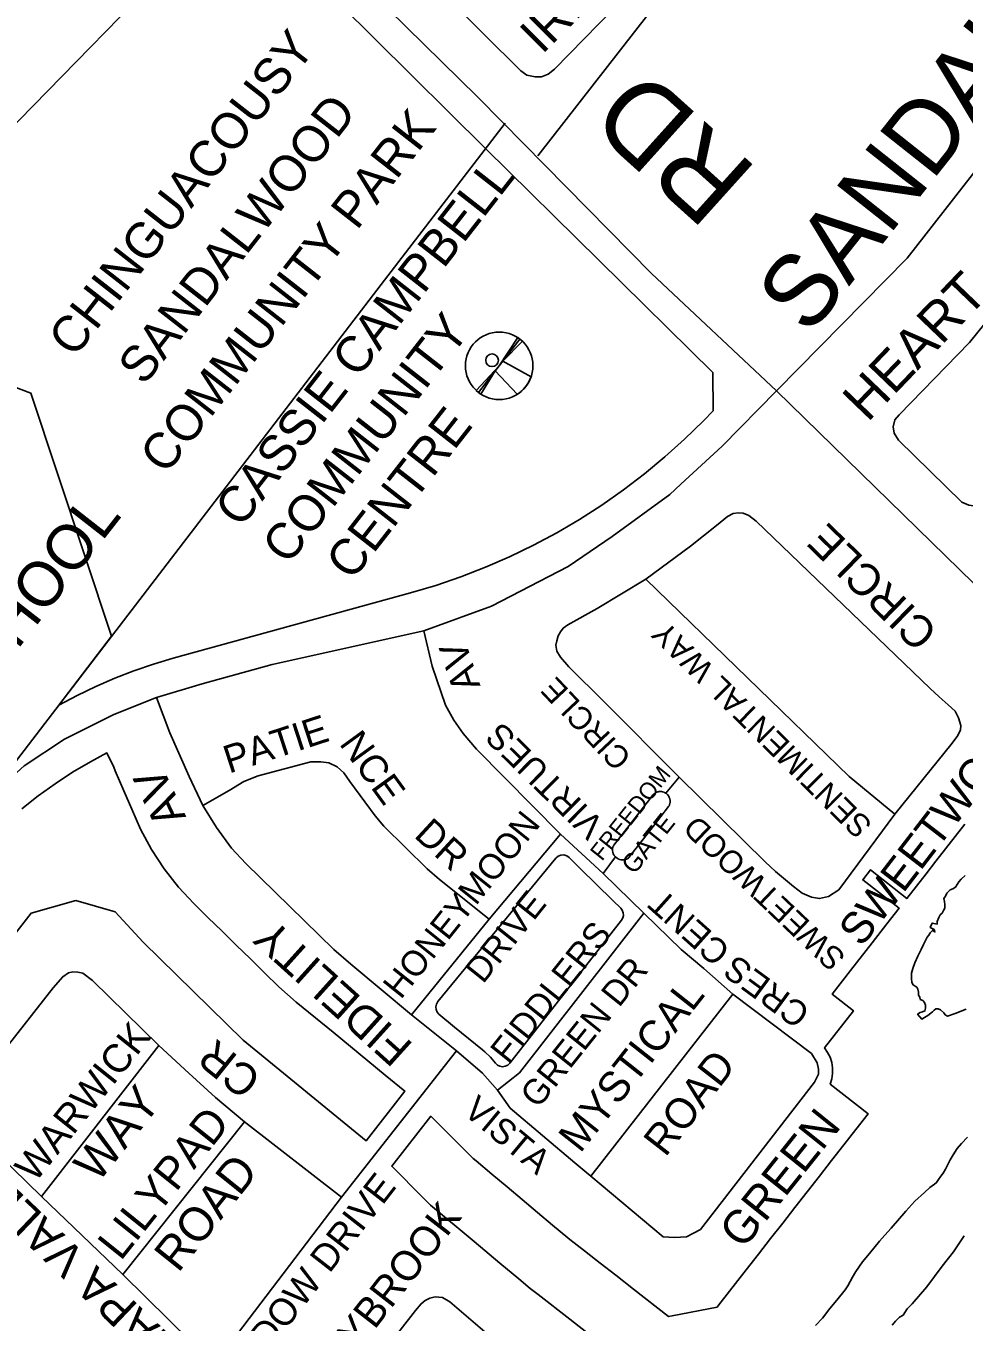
# Model space of a CAD drawing. Extents: x 586326 to 623965, y 4819854 to 4857850.
# Drawn here: x 594445 to 594966, y 4838360 to 4839080 of the extents above; entities that cross this region are included whole.
import ezdxf

# ---------------------------------------------------------------- set-up
doc = ezdxf.new("R2010")
doc.units = 0
for name, color, linetype in [('Lots_Concessions', 7, 'Continuous'), ('Major Rds and Hwys', 7, 'Continuous'), ('Major Rds Lbls', 7, 'Continuous'), ('Minor Rd Lbls', 7, 'Continuous'), ('Minor Rds', 7, 'Continuous'), ('Park Lbls', 7, 'Continuous'), ('Park Outlines', 7, 'Continuous'), ('Rec Lbls', 7, 'Continuous'), ('Rec Syms', 7, 'Continuous'), ('School Syms_Lbls', 7, 'Continuous'), ('SWM Ponds', 7, 'Continuous')]:
    doc.layers.add(name, color=color, linetype=linetype)

msp = doc.modelspace()

# ---------------------------------------------------------------- linework, layer by layer
at = {"layer": 'Lots_Concessions'}
for p, q in [((594729.47, 4839007.45), (595156.29, 4839555.22)), ((594642.61, 4838935.95), (594711.39, 4839025.63)), ((594295.72, 4838483.65), (594642.61, 4838935.95))]:
    msp.add_line(p, q, dxfattribs=at)
at = {"layer": 'Major Rds and Hwys'}
for points in [[(594861.99, 4838876.99), (594934.54, 4838950.7), (595088.89, 4839148.46)], [(594709.8, 4839026.23), (594696.13, 4839040.1), (594606.93, 4839127.81)], [(594861.99, 4838876.99), (594792.7, 4838942.09), (594709.8, 4839026.23)], [(594808.99, 4838825.16), (594831.95, 4838846.26), (594861.99, 4838876.99)], [(595281.37, 4838462.67), (595165.16, 4838580.18), (595155.16, 4838590.01), (595018.37, 4838724.46), (594861.99, 4838876.99)], [(594666.27, 4838743.78), (594703.78, 4838757.46), (594746.36, 4838779.49), (594770.84, 4838796.08), (594802.91, 4838819.41), (594808.99, 4838825.16)], [(594517.84, 4838706.7), (594543.23, 4838714.45), (594582.03, 4838725.17), (594666.27, 4838743.78)], [(594290.63, 4838488.36), (594398.62, 4838625.17), (594419.01, 4838646.13), (594444.39, 4838668.83), (594466.8, 4838683.62), (594494.09, 4838697.43), (594517.84, 4838706.7)]]:
    msp.add_lwpolyline(points, dxfattribs=at)
at = {"layer": 'Minor Rds'}
for points in [[(594947.94, 4839266.3), (594874.03, 4839214.2), (594868.8, 4839209.7), (594863.92, 4839203.89), (594791.44, 4839110.68), (594785.39, 4839103.38), (594779.91, 4839097.69), (594738.78, 4839055.6), (594735.26, 4839052.85), (594731.6, 4839051.24), (594728.13, 4839051.2), (594723.38, 4839052.16), (594720.18, 4839054.66), (594678.5, 4839096.03)], [(595045.04, 4838887.27), (595022.97, 4838860.3), (594980.45, 4838817.27), (594976.3, 4838814.28), (594972.51, 4838813.03), (594968.85, 4838813.48), (594964.93, 4838815.14), (594929.81, 4838849.61), (594927.29, 4838853.58), (594926.76, 4838857.01), (594927.75, 4838860.85), (594930.12, 4838863.62), (594969.14, 4838903.81), (594981.57, 4838919.2), (595018.06, 4838965.39)], [(594828.64, 4838802.32), (594834.83, 4838807.27), (594837.99, 4838808.92), (594840.73, 4838809.26), (594843.55, 4838809.18), (594846.73, 4838807.81), (594850.79, 4838804.64), (594947.29, 4838711.7), (594952.33, 4838707.12), (594957.35, 4838702.74), (594961.18, 4838699.19), (594963.07, 4838695.53), (594964.32, 4838691.24), (594964.21, 4838688.92), (594962.67, 4838685.78), (594959.66, 4838681.49), (594927.66, 4838641.98)], [(594789.42, 4838772.42), (594814.37, 4838790.77), (594828.64, 4838802.32)], [(594808, 4838662.64), (594766.39, 4838704.31), (594746.74, 4838723.82), (594742.18, 4838729.15), (594740.04, 4838732.6), (594739.58, 4838735.78), (594740, 4838738.28), (594740.85, 4838741.04), (594742.1, 4838743.24), (594743.63, 4838745.35), (594746.25, 4838747.19), (594762.49, 4838756.2), (594789.42, 4838772.42)], [(594927.66, 4838641.98), (594902.35, 4838662.94), (594789.42, 4838772.42)], [(594742.13, 4838630.93), (594695.54, 4838678.14), (594688.02, 4838686.77), (594682.98, 4838694.16), (594678.33, 4838702.62), (594670.78, 4838724.16), (594666.27, 4838743.78)], [(594543.46, 4838646.84), (594536.05, 4838663), (594525.26, 4838687.23), (594517.84, 4838706.7)], [(594702.48, 4838583.71), (594674.86, 4838605.76), (594668.05, 4838611.76), (594643.98, 4838635.4), (594639.27, 4838641.15), (594625.18, 4838660.21), (594621.76, 4838664.95), (594618.12, 4838668.25), (594613.46, 4838670.52), (594609.12, 4838671.15), (594603.57, 4838671.11), (594574.2, 4838663.24), (594566.31, 4838660.21), (594558.16, 4838655.08), (594543.46, 4838646.84)], [(594800.51, 4838653.7), (594808, 4838662.64)], [(594808, 4838662.64), (594855.67, 4838615.63), (594861.48, 4838610.18), (594871.5, 4838601.9), (594876.33, 4838598.12), (594881.48, 4838595.93), (594885.94, 4838595.19), (594890.94, 4838596.31), (594896.64, 4838600.1), (594927.66, 4838641.98)], [(594772.67, 4838618.3), (594772.27, 4838618.74), (594772.13, 4838618.9), (594772, 4838619.06), (594771.89, 4838619.24), (594771.79, 4838619.43), (594771.45, 4838620.09), (594771.36, 4838620.28), (594771.29, 4838620.48), (594771.23, 4838620.68), (594771.18, 4838620.89), (594771.04, 4838621.62), (594771.01, 4838621.83), (594770.99, 4838622.04), (594770.99, 4838622.25), (594771.01, 4838622.46), (594771.08, 4838623.2), (594771.11, 4838623.44), (594771.16, 4838623.67), (594771.23, 4838623.91), (594771.32, 4838624.13), (594771.43, 4838624.35), (594771.55, 4838624.55), (594771.69, 4838624.75), (594780.23, 4838635.76), (594780.24, 4838635.77), (594791.5, 4838650.13), (594793.37, 4838652.7), (594793.52, 4838652.9), (594793.7, 4838653.08), (594793.88, 4838653.25), (594794.08, 4838653.4), (594794.7, 4838653.83), (594794.9, 4838653.96), (594795.1, 4838654.07), (594795.31, 4838654.16), (594795.52, 4838654.24), (594796.25, 4838654.46), (594796.47, 4838654.52), (594796.69, 4838654.56), (594796.92, 4838654.59), (594797.15, 4838654.6), (594797.91, 4838654.59), (594798.14, 4838654.59), (594798.36, 4838654.56), (594798.59, 4838654.51), (594798.81, 4838654.45), (594799.53, 4838654.22), (594799.75, 4838654.15), (594799.95, 4838654.05), (594800.51, 4838653.7)], [(594800.51, 4838653.7), (594800.97, 4838653.38), (594801.15, 4838653.24), (594801.32, 4838653.09), (594801.48, 4838652.93), (594801.62, 4838652.75), (594802.08, 4838652.15), (594802.22, 4838651.96), (594802.33, 4838651.76), (594802.43, 4838651.56), (594802.52, 4838651.34), (594802.78, 4838650.63), (594802.85, 4838650.41), (594802.9, 4838650.19), (594802.94, 4838649.96), (594802.95, 4838649.74), (594802.98, 4838648.98), (594802.98, 4838648.75), (594802.97, 4838648.52), (594802.93, 4838648.3), (594802.88, 4838648.07), (594802.68, 4838647.34), (594802.61, 4838647.12), (594802.52, 4838646.9), (594802.42, 4838646.68), (594802.3, 4838646.48), (594802.16, 4838646.29), (594793.56, 4838635.2), (594793.55, 4838635.19), (594780.14, 4838618.05), (594779.97, 4838617.86), (594779.79, 4838617.68), (594779.59, 4838617.51), (594779.38, 4838617.37), (594779.15, 4838617.24), (594778.92, 4838617.13), (594778.68, 4838617.04), (594777.97, 4838616.82), (594777.77, 4838616.76), (594777.56, 4838616.72), (594777.35, 4838616.69), (594777.14, 4838616.68), (594776.39, 4838616.66), (594776.18, 4838616.67), (594775.97, 4838616.68), (594775.76, 4838616.72), (594775.56, 4838616.76), (594774.84, 4838616.95), (594774.64, 4838617.01), (594774.44, 4838617.09), (594774.25, 4838617.18), (594774.06, 4838617.28), (594773.56, 4838617.65), (594772.67, 4838618.3)], [(594659.42, 4838530.66), (594625.75, 4838558.8), (594616.23, 4838566.93), (594567.51, 4838614.65), (594559.49, 4838623.22), (594551.12, 4838634.59), (594543.46, 4838646.84)], [(594702.48, 4838583.71), (594742.13, 4838630.93)], [(594765.84, 4838609.18), (594742.13, 4838630.93)], [(594765.84, 4838609.18), (594772.67, 4838618.3)], [(594788.42, 4838587.01), (594765.84, 4838609.18)], [(594659.42, 4838530.66), (594702.48, 4838583.71)], [(594707.2, 4838488.88), (594719.3, 4838498.54), (594788.42, 4838587.01)], [(594837.87, 4838542.15), (594821.68, 4838556.46), (594809.15, 4838566.99), (594788.42, 4838587.01)], [(594454.03, 4838429.74), (594414.11, 4838468.41), (594411.55, 4838472.03), (594410.72, 4838474.82), (594410.55, 4838477.78), (594410.86, 4838480.36), (594411.95, 4838483.19), (594413.98, 4838486.66), (594460.46, 4838545.71), (594465.77, 4838551.84), (594468.92, 4838553.91), (594471.4, 4838554.46), (594474.1, 4838554.4), (594476.92, 4838553.74), (594482.32, 4838549.69), (594519.04, 4838513.62)], [(594758.93, 4838441.11), (594837.87, 4838542.15)], [(594837.87, 4838542.15), (594881.44, 4838509.24), (594884.62, 4838503.93), (594885.36, 4838500.55), (594885.39, 4838497.71), (594883.09, 4838493.31), (594819.79, 4838411.58), (594812.08, 4838407.47), (594805.5, 4838406.98), (594799.12, 4838407.47), (594758.93, 4838441.11)], [(594684.29, 4838510.69), (594659.42, 4838530.66)], [(594454.03, 4838429.74), (594519.04, 4838513.62)], [(594566.63, 4838471.25), (594550.54, 4838484.86), (594535.79, 4838498.2), (594519.04, 4838513.62)], [(594620.55, 4838429.39), (594684.29, 4838510.69)], [(594707.2, 4838488.88), (594698.78, 4838498.24), (594684.29, 4838510.69)], [(594758.93, 4838441.11), (594750.12, 4838448.55), (594714.12, 4838478.94), (594707.2, 4838488.88)], [(594499.13, 4838386.44), (594566.63, 4838471.25)], [(594620.55, 4838429.39), (594566.63, 4838471.25)], [(594499.13, 4838386.44), (594454.03, 4838429.74)], [(594549.79, 4838336.5), (594620.55, 4838429.39)], [(594549.79, 4838336.5), (594499.13, 4838386.44)], [(594645.06, 4838242.82), (594713.21, 4838328.18), (594715.48, 4838333.06), (594715.81, 4838337.42), (594714.37, 4838342.13), (594711.75, 4838344.69), (594680.75, 4838371.33), (594676.65, 4838373.85), (594672.62, 4838374.17), (594669.5, 4838373.44), (594666.95, 4838372.16), (594664.71, 4838370.3), (594661.64, 4838366.5), (594599.44, 4838286.89)]]:
    msp.add_lwpolyline(points, dxfattribs=at)
at = {"layer": 'Park Outlines'}
for points in [[(594355.24, 4838910.92), (594448.07, 4838875.8), (594492.92, 4838740.76), (594463.65, 4838702.59), (594473.77, 4838707.98), (594484.1, 4838712.95), (594494.61, 4838717.51), (594505.31, 4838721.65), (594516.16, 4838725.35), (594527.15, 4838728.62), (594658.77, 4838764.86), (594672.84, 4838769.04), (594686.73, 4838773.78), (594700.42, 4838779.09), (594713.88, 4838784.93), (594727.1, 4838791.32), (594740.05, 4838798.24), (594752.71, 4838805.67), (594765.05, 4838813.61), (594777.07, 4838822.03), (594788.74, 4838830.94), (594800.04, 4838840.31), (594810.96, 4838850.13), (594821.46, 4838860.38), (594826.94, 4838865.94), (594826.78, 4838887.14), (594700.51, 4839011.49), (594639.25, 4839072.23), (594561.14, 4839149.7), (594409.35, 4838994.44)], [(594368.63, 4838485), (594448.2, 4838587.17), (594473.04, 4838594.1), (594494.93, 4838587.81), (594510.36, 4838571.08), (594566, 4838516.58), (594634.16, 4838460.77), (594655.66, 4838488.38), (594644.85, 4838497.23), (594635.18, 4838505.15), (594625.52, 4838513.07), (594615.85, 4838520.98), (594606.18, 4838528.9), (594595.41, 4838537.72), (594585.69, 4838546.27), (594577.83, 4838553.96), (594569.98, 4838561.66), (594562.12, 4838569.35), (594554.26, 4838577.05), (594546.41, 4838584.74), (594538.55, 4838592.44), (594530.04, 4838601.51), (594522.08, 4838611.62), (594515.06, 4838622.38), (594508.91, 4838633.65), (594504.1, 4838644.84), (594499.75, 4838654.94), (594494.94, 4838666.13), (594494.94, 4838666.13), (594494.11, 4838668.07), (594490.32, 4838676.02), (594481.2, 4838671.17), (594471.21, 4838665.28), (594461.5, 4838658.93), (594452.1, 4838652.15), (594443.02, 4838644.93)], [(594966.57, 4838636.42), (594961.21, 4838629.57), (594955.86, 4838622.71), (594950.5, 4838615.86), (594945.15, 4838609), (594939.79, 4838602.15), (594934.44, 4838595.29), (594914.23, 4838611.08), (594909.92, 4838605.56), (594930.13, 4838589.78), (594923.36, 4838581.11), (594915.16, 4838570.61), (594903.18, 4838555.28), (594892.94, 4838542.17), (594897.94, 4838538.27), (594904.79, 4838532.92), (594888.7, 4838512.31), (594890.44, 4838509.81), (594891.78, 4838507.08), (594892.7, 4838504.18), (594893.17, 4838501.17), (594893.18, 4838498.13), (594892.73, 4838495.12), (594891.84, 4838492.21), (594912.91, 4838475.75), (594906.14, 4838467.08), (594899.37, 4838458.42), (594892.6, 4838449.75), (594885.84, 4838441.09), (594879.07, 4838432.42), (594872.3, 4838423.76), (594865.53, 4838415.09), (594858.76, 4838406.43), (594851.99, 4838397.76), (594845.22, 4838389.1), (594830.08, 4838369.7), (594829.02, 4838368.36), (594804.15, 4838363.63), (594802.04, 4838363.23), (594782.64, 4838378.39), (594772.75, 4838386.11), (594764.08, 4838392.88), (594755.42, 4838399.65), (594747.33, 4838405.96), (594746.2, 4838406.91), (594737.77, 4838413.97), (594729.33, 4838421.03), (594720.9, 4838428.09), (594712.47, 4838435.16), (594704.03, 4838442.22), (594695.29, 4838449.53), (594693.65, 4838450.91), (594686.34, 4838458.21), (594678.56, 4838465.97), (594670.11, 4838474.4), (594648.45, 4838446.59), (594665.92, 4838429.16), (594670.02, 4838425.06), (594694.11, 4838404.9), (594708.5, 4838392.84), (594719, 4838384.05), (594725.33, 4838378.76), (594729.63, 4838375.4), (594747.22, 4838361.66), (594768.77, 4838344.82)]]:
    msp.add_lwpolyline(points, dxfattribs=at)
msp.add_lwpolyline([(594739.56, 4838617.65), (594674, 4838537.97), (594673.21, 4838536.63), (594672.87, 4838535.11), (594673.01, 4838533.56), (594673.63, 4838532.13), (594674.65, 4838530.96), (594683.3, 4838523.88), (594698.78, 4838511.21), (594700.1, 4838510.12), (594703.27, 4838507.18), (594706.05, 4838503.87), (594707.14, 4838502.81), (594708.49, 4838502.13), (594709.99, 4838501.88), (594711.49, 4838502.09), (594712.86, 4838502.74), (594713.97, 4838503.78), (594776, 4838583.19), (594776.72, 4838584.44), (594777.04, 4838585.85), (594776.95, 4838587.3), (594776.44, 4838588.66), (594775.57, 4838589.81), (594775.56, 4838589.83), (594771.22, 4838594.09), (594752.94, 4838612.1), (594746.91, 4838618.04), (594745.56, 4838618.98), (594743.97, 4838619.43), (594742.33, 4838619.34), (594740.8, 4838618.72)], close=True, dxfattribs=at)
at = {"layer": 'Rec Syms'}
for p, q in [((594719.63, 4838905.67), (594696.56, 4838876.14)), ((594696.56, 4838876.14), (594705.86, 4838888.05))]:
    msp.add_line(p, q, dxfattribs=at)
msp.add_lwpolyline([(594708, 4838890.93), (594695.27, 4838877.25), (594696.56, 4838876.14), (594697.88, 4838875.2), (594705.86, 4838888.05), (594718.13, 4838875.09), (594718.8, 4838875.53), (594719.71, 4838876.2), (594720.25, 4838876.65), (594720.33, 4838876.74), (594720.67, 4838877.01), (594721.48, 4838877.79), (594722.16, 4838878.52), (594722.86, 4838879.37), (594723.38, 4838880.08), (594723.9, 4838880.89), (594724.17, 4838881.29), (594724.51, 4838881.88), (594724.91, 4838882.62), (594725.14, 4838883.17), (594725.81, 4838884.72), (594710.05, 4838893.55), (594721, 4838904.51), (594719.63, 4838905.67), (594718.38, 4838906.55)], close=True, dxfattribs=at)
for centre, radius in [((594708.09, 4838890.91), 18.74), ((594704.14, 4838893.95), 3.5)]:
    msp.add_circle(centre, radius, dxfattribs=at)
at = {"layer": 'SWM Ponds'}
for points in [[(594966.71, 4838607.97), (594964.53, 4838605.92), (594963.19, 4838604.39), (594962.32, 4838602.91), (594961.43, 4838601.59), (594959.94, 4838600.59), (594958.39, 4838600.08), (594956.69, 4838598.1), (594955.84, 4838596.46), (594955.02, 4838595.23), (594955.4, 4838593.49), (594955.45, 4838591.72), (594955.44, 4838589.86), (594954.8, 4838588.49), (594953.93, 4838587.01), (594952.83, 4838586.15), (594952.21, 4838584.62), (594951.3, 4838582.37), (594951.27, 4838581.03), (594948.54, 4838581.59), (594947.38, 4838579.18), (594949.63, 4838578), (594950.03, 4838576.68), (594948.64, 4838577.48), (594947.28, 4838576.1), (594946.55, 4838574.8), (594945.78, 4838573.82), (594944.79, 4838572), (594943.7, 4838569.68), (594942.42, 4838566.94), (594940.45, 4838563.31), (594938.81, 4838559.55), (594937.66, 4838556.42), (594937.01, 4838553.76), (594937.05, 4838550.85), (594937.16, 4838548.61), (594937.97, 4838547.25), (594938.96, 4838546.48), (594939.99, 4838545.96), (594940.54, 4838544.82), (594940.8, 4838543.32), (594940.93, 4838541.64), (594941.63, 4838540.51), (594941.88, 4838539.17), (594943.25, 4838538.53), (594944.27, 4838537.44), (594944.76, 4838536.05), (594944.73, 4838534.35), (594944.43, 4838532.86), (594943.19, 4838532.38), (594941.87, 4838531.98), (594940.38, 4838530.99), (594942.82, 4838528.22), (594944.24, 4838529.12), (594946.03, 4838530.31), (594947.65, 4838531.64), (594948.68, 4838532.41), (594949.63, 4838533.25), (594950.59, 4838533.94), (594951.73, 4838533.92), (594953.01, 4838533.35), (594954.98, 4838531.81), (594955.68, 4838530.69), (594956.98, 4838529.96), (594961.25, 4838531.37), (594967.42, 4838533.74)], [(594968.06, 4838462.67), (594964.76, 4838459.19), (594962.28, 4838456.38), (594960.12, 4838452.88), (594958.43, 4838450.16), (594957.2, 4838447.66), (594955.83, 4838444.99), (594954.56, 4838442.81), (594953.32, 4838441.04), (594951.92, 4838439.25), (594950.91, 4838437.59), (594949.73, 4838436.63), (594947.13, 4838434.77), (594944.14, 4838432.06), (594938.91, 4838427.21), (594933.76, 4838421.72), (594925.71, 4838412.16), (594922.13, 4838408.32), (594919.14, 4838405.04), (594913.59, 4838398.13), (594909.78, 4838393.61), (594906.15, 4838388.23), (594904.27, 4838385.09), (594901.7, 4838380.32), (594900.2, 4838378.03), (594895.57, 4838372.28), (594891.68, 4838367.68), (594887.64, 4838362.33), (594883.7, 4838358.2)], [(594926.17, 4838358.32), (594928.15, 4838360.67), (594930.3, 4838362.87), (594932.28, 4838363.93), (594934.6, 4838367.45), (594937.33, 4838370.21), (594945.47, 4838379.71), (594954.02, 4838391.19), (594960.33, 4838399.09), (594966.28, 4838407.99)]]:
    msp.add_lwpolyline(points, dxfattribs=at)

# ---------------------------------------------------------------- texts
at = {"layer": 'Major Rds Lbls'}
for s, height, rotation, p in [('SANDALWOOD     ', 39.96, 51.62538, (594880.1, 4838906.84)), ('RD', 45.354, 137.99943, (594852.37, 4838999.49))]:
    msp.add_text(s, height=height, rotation=rotation, dxfattribs=at).set_placement(p)
at = {"layer": 'Minor Rd Lbls'}
for s, height, rotation, p in [('IRENE', 19.8, 45.25621, (594731.96, 4839063.33)), ('HEART', 21.6, 46.20032, (594912.57, 4838859.12)), ('CIRCLE', 17.705, 135.72478, (594952.52, 4838743.89)), ('SENTIMENTAL WAY', 12.6576, 135.43178, (594915.89, 4838636.58)), ('AV', 15.39, 108.53966, (594697.73, 4838713.22)), ('CIRCLE', 12.658, 133.33187, (594782.18, 4838673.83)), ('PATIE', 15.39, 18.01376, (594558.08, 4838664.51)), ('SWEETWOOD ', 17.558, 52.41414, (594909.3, 4838567.75)), ('NCE', 15.39, 306.01085, (594618.91, 4838681.08)), ('VIRTUES', 14.025, 135.48733, (594767.17, 4838636.87)), ('FREEDOM', 9.278, 51.3286, (594765.11, 4838615.57)), ('AV', 18, 115.30839, (594534.41, 4838640.54)), ('HONEYMOON', 14.025, 51.3286, (594653.46, 4838538.76)), ('DR', 15.39, 317.34322, (594660.24, 4838629.69)), ('GATE', 10.228, 51.3286, (594783.08, 4838608.09)), ('SWEETWOOD', 12.658, 136.4497, (594901.14, 4838563.18)), ('DRIVE', 14.025, 51.3286, (594699.13, 4838547.38)), ('CENT', 14.025, 138.18089, (594837.27, 4838567.15)), ('FIDDLERS', 14.025, 51.3286, (594713.09, 4838502.78)), ('FIDELITY', 18, 137.96759, (594660.97, 4838514.09)), ('GREEN DR', 14.025, 51.3286, (594729.66, 4838478.11)), ('CRES', 14.025, 143.65516, (594881.62, 4838533.63)), ('MYSTICAL', 16.83, 51.65683, (594753.01, 4838453.39)), ('WARWICK ', 15.753, 51.3286, (594450.38, 4838437)), ('CR', 17.712, 141.34042, (594577.12, 4838496.69)), ('ROAD', 16.83, 52.13247, (594800.32, 4838451.23)), ('WAY', 18.752, 51.3286, (594485.28, 4838436.86)), ('VISTA', 14.025, 320.19928, (594687.45, 4838476.02)), ('LILYPAD', 17.859, 51.3286, (594497.93, 4838393.59)), ('GREEN', 18.513, 51.3286, (594843.49, 4838399.97)), ('NAPA VALLEY', 18.5551, 136.34038, (594533.23, 4838345.49)), ('ROAD', 18.752, 51.3286, (594529.85, 4838386.99)), ('WETMEADOW DRIVE', 15, 52.09929, (594526.2, 4838274.21)), ('MISTYBROOK', 16.5, 52.09929, (594597.46, 4838302.31))]:
    msp.add_text(s, height=height, rotation=rotation, dxfattribs=at).set_placement(p)
at = {"layer": 'Park Lbls'}
for s, p in [('CHINGUACOUSY', (594472.16, 4838894.76)), ('SANDALWOOD', (594510.84, 4838879.32)), ('COMMUNITY PARK', (594522.97, 4838829.89))]:
    msp.add_text(s, height=19.992, rotation=52.00002, dxfattribs=at).set_placement(p)
at = {"layer": 'Rec Lbls'}
for s, p in [('CASSIE CAMPBELL', (594564.58, 4838800.26)), ('COMMUNITY', (594590.85, 4838779.74)), ('  CENTRE', (594617.11, 4838759.22))]:
    msp.add_text(s, height=20, rotation=52.00002, dxfattribs=at).set_placement(p)
at = {"layer": 'School Syms_Lbls'}
msp.add_text('SECONDARY SCHOOL', height=25, rotation=52.00002, dxfattribs=at).set_placement((594275.87, 4838522.17))

doc.saveas('drawing.dxf')
